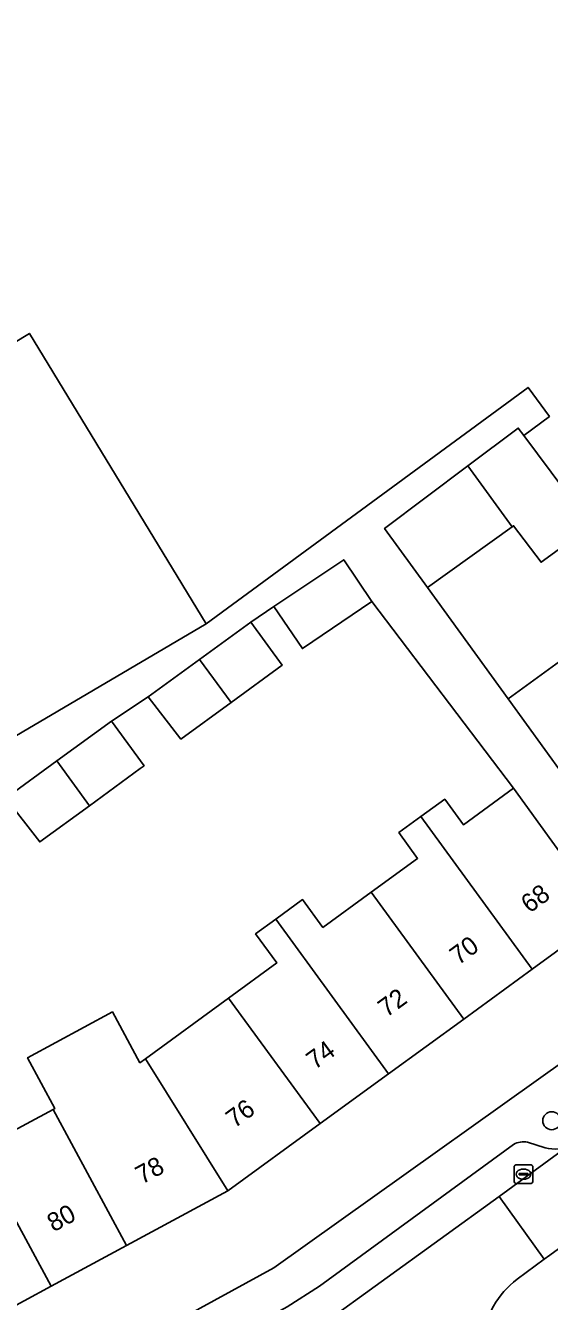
# Model space of a CAD drawing. Extents: x 159817 to 160765, y 380688 to 381638.
# Drawn here: x 159915.8 to 159944.3, y 381366.6 to 381436.1 of the extents above; entities that cross this region are included whole.
import ezdxf

# ---------------------------------------------------------------- set-up
doc = ezdxf.new("R2010")
doc.units = 0
for name, color, linetype in [('IMGEO_Boom', 7, 'Continuous'), ('IMGEO_Erf', 7, 'Continuous'), ('IMGEO_Kolk', 7, 'Continuous'), ('IMGEO_Pand', 7, 'Continuous'), ('IMGEO_Pand_nummerreeks', 7, 'Continuous'), ('IMGEO_Parkeervlak_open', 7, 'Continuous'), ('IMGEO_Rijbaan_lokaal_open', 7, 'Continuous'), ('IMGEO_Voetpad_open', 7, 'Continuous')]:
    doc.layers.add(name, color=color, linetype=linetype)

msp = doc.modelspace()

# ---------------------------------------------------------------- linework, layer by layer
at = {"layer": 'IMGEO_Boom'}
msp.add_circle((159944.457, 381376.478), 0.489, dxfattribs=at)
at = {"layer": 'IMGEO_Erf'}
for points in [[(159878.875, 381396.888), (159916.025, 381419.326), (159925.649, 381403.516), (159943.166, 381416.395), (159944.328, 381414.815), (159942.937, 381413.777), (159946.609, 381408.857), (159943.877, 381406.876), (159942.384, 381408.857), (159942.302, 381408.798), (159937.694, 381405.502), (159942.078, 381399.432), (159946.679, 381402.779)], [(159914.391, 381375.519), (159917.308, 381377.095), (159917.41, 381377.15), (159915.922, 381379.906), (159920.542, 381382.402), (159922.036, 381379.635), (159922.336, 381379.854), (159926.865, 381383.154), (159929.485, 381385.063), (159928.333, 381386.644), (159929.444, 381387.453), (159930.895, 381388.51), (159931.998, 381386.996), (159934.631, 381388.914), (159937.157, 381390.754), (159936.135, 381392.156), (159937.332, 381393.028), (159938.635, 381393.977), (159939.647, 381392.588), (159942.37, 381394.572), (159934.668, 381404.735), (159930.882, 381402.174), (159929.335, 381404.461), (159928.075, 381403.617), (159929.786, 381401.273), (159927.012, 381399.247), (159924.272, 381397.247), (159922.493, 381399.54), (159920.495, 381398.229), (159922.27, 381395.797), (159922.061, 381395.644), (159919.287, 381393.619), (159916.589, 381391.649), (159914.744, 381394.028)]]:
    msp.add_lwpolyline(points, dxfattribs=at)
msp.add_lwpolyline([(159948.981, 381382.473), (159950.421, 381383.521), (159947.411, 381387.653), (159943.387, 381384.722), (159939.664, 381382.009), (159935.58, 381379.034), (159931.849, 381376.317), (159926.83, 381372.66), (159921.311, 381369.679), (159917.205, 381367.462), (159912.776, 381365.069), (159907.785, 381362.373), (159902.815, 381359.689), (159897.692, 381356.922), (159900.122, 381352.484), (159929.338, 381368.476)], close=True, dxfattribs=at)
at = {"layer": 'IMGEO_Kolk'}
for p, q in [((159942.419, 381373.142), (159942.419, 381373.994)), ((159942.494, 381374.068), (159943.346, 381374.068)), ((159942.721, 381373.611), (159943.119, 381373.611)), ((159942.907, 381373.848), (159942.932, 381373.848)), ((159943.42, 381373.994), (159943.42, 381373.142)), ((159943.346, 381373.068), (159942.494, 381373.068)), ((159942.678, 381373.562), (159942.678, 381373.574)), ((159943.116, 381373.525), (159942.718, 381373.525)), ((159942.93, 381373.288), (159942.905, 381373.288)), ((159943.162, 381373.574), (159943.162, 381373.562))]:
    msp.add_line(p, q, dxfattribs=at)
for points in [[(159942.419, 381373.142), (159942.419, 381373.994)], [(159942.494, 381374.068), (159943.346, 381374.068)], [(159943.42, 381373.994), (159943.42, 381373.142)], [(159943.346, 381373.068), (159942.494, 381373.068)]]:
    msp.add_lwpolyline(points, dxfattribs=at)
for centre, radius, start, end in [((159942.496, 381373.992), 0.0765, 91.55205, 178.44795), ((159942.496, 381373.992), 0.0765, 91.55205, 178.44795), ((159942.718, 381373.571), 0.0403, 85.87752, 175.75265), ((159943.123, 381373.573), 0.0386, 1.73085, 96.63898), ((159943.344, 381373.992), 0.0765, 1.55205, 88.44795), ((159943.344, 381373.992), 0.0765, 1.55205, 88.44795), ((159942.496, 381373.144), 0.0765, 181.55205, 268.44795), ((159942.496, 381373.144), 0.0765, 181.55205, 268.44795), ((159942.715, 381373.561), 0.0366, 178.93798, 274.71019), ((159943.119, 381373.568), 0.043, 264.86636, 352.45326), ((159943.344, 381373.144), 0.0765, 271.55205, 358.44795), ((159943.344, 381373.144), 0.0765, 271.55205, 358.44795)]:
    msp.add_arc(centre, radius, start, end, dxfattribs=at)
for centre, major_axis, ratio, start_param, end_param in [((159942.906, 381373.568), (-0.387, 0.002), 0.722429, 4.712389, 7.853982), ((159942.931, 381373.568), (-0.39, 0.002), 0.717154, 1.570796, 4.712389)]:
    msp.add_ellipse(centre, major_axis=major_axis, ratio=ratio, start_param=start_param, end_param=end_param, dxfattribs=at)
at = {"layer": 'IMGEO_Pand'}
for points in [[(159925.649, 381403.516), (159916.025, 381419.326), (159878.875, 381396.888), (159888.162, 381381.468), (159889.129, 381382.037)], [(159942.937, 381413.777), (159942.638, 381414.177), (159939.889, 381412.116), (159942.302, 381408.798), (159942.384, 381408.857), (159943.877, 381406.876), (159946.609, 381408.857)], [(159939.889, 381412.116), (159935.361, 381408.72), (159937.694, 381405.502), (159942.302, 381408.798)], [(159933.133, 381407.006), (159929.335, 381404.461), (159930.882, 381402.174), (159934.668, 381404.735)], [(159928.075, 381403.617), (159925.29, 381401.583), (159927.012, 381399.247), (159929.786, 381401.273)], [(159946.843, 381402.553), (159946.679, 381402.779), (159942.078, 381399.432), (159946.086, 381393.922), (159949.028, 381389.878), (159953.628, 381393.224)], [(159925.29, 381401.583), (159922.493, 381399.54), (159924.272, 381397.247), (159927.012, 381399.247)], [(159920.495, 381398.229), (159917.522, 381396.057), (159919.287, 381393.619), (159922.061, 381395.644), (159922.27, 381395.797)], [(159917.522, 381396.057), (159914.744, 381394.028), (159916.589, 381391.649), (159919.287, 381393.619)], [(159937.332, 381393.028), (159943.387, 381384.722), (159947.411, 381387.653), (159944.466, 381391.695), (159942.37, 381394.572), (159939.647, 381392.588), (159938.635, 381393.977)], [(159939.664, 381382.009), (159943.387, 381384.722), (159937.332, 381393.028), (159936.135, 381392.156), (159937.157, 381390.754), (159934.631, 381388.914)], [(159934.631, 381388.914), (159931.998, 381386.996), (159930.895, 381388.51), (159929.444, 381387.453), (159935.58, 381379.034), (159939.664, 381382.009)], [(159931.849, 381376.317), (159935.58, 381379.034), (159929.444, 381387.453), (159928.333, 381386.644), (159929.485, 381385.063), (159926.865, 381383.154)], [(159931.849, 381376.317), (159926.865, 381383.154), (159922.336, 381379.854), (159926.83, 381372.66)], [(159917.308, 381377.095), (159921.311, 381369.679), (159926.83, 381372.66), (159922.336, 381379.854), (159922.036, 381379.635), (159920.542, 381382.402), (159915.922, 381379.906), (159917.41, 381377.15)], [(159912.076, 381376.962), (159917.205, 381367.462), (159921.311, 381369.679), (159917.308, 381377.095), (159914.391, 381375.519), (159913.265, 381377.604)], [(159912.076, 381376.962), (159907.792, 381374.648), (159907.648, 381374.57), (159912.776, 381365.069), (159917.205, 381367.462)]]:
    msp.add_lwpolyline(points, close=True, dxfattribs=at)
at = {"layer": 'IMGEO_Parkeervlak_open'}
for points in [[(159942.382, 381375.189), (159931.813, 381367.471), (159930.062, 381366.351), (159925.659, 381363.938)], [(159941.589, 381372.352), (159945.51, 381375.214)], [(159944.096, 381375.007), (159943.137, 381375.314)], [(159929.496, 381363.976), (159931.961, 381365.382), (159941.589, 381372.352)]]:
    msp.add_lwpolyline(points, dxfattribs=at)
for centre, radius, start, end in [((159942.956, 381374.062), 1.265, 81.79187, 117.00969), ((159944.582, 381376.619), 1.683, 253.21214, 303.44497)]:
    msp.add_arc(centre, radius, start, end, dxfattribs=at)
at = {"layer": 'IMGEO_Rijbaan_lokaal_open'}
msp.add_lwpolyline([(159967.167, 381385.74), (159964.661, 381389.178), (159949.818, 381378.361), (159945.51, 381375.214), (159941.589, 381372.352), (159944.041, 381368.933), (159944.348, 381369.151), (159953.636, 381375.926)], close=True, dxfattribs=at)
for points in [[(159941.589, 381372.352), (159931.961, 381365.382), (159929.496, 381363.976)], [(159944.041, 381368.933), (159941.589, 381372.352)], [(159942.572, 381367.853), (159944.041, 381368.933)]]:
    msp.add_lwpolyline(points, dxfattribs=at)
msp.add_arc((159945.591, 381363.925), 4.954, 127.55165, 217.93343, dxfattribs=at)
at = {"layer": 'IMGEO_Voetpad_open'}
for points in [[(160025.115, 381437.941), (160006.457, 381424.324), (160006.453, 381424.321), (160003.64, 381422.268), (160000, 381419.611), (159973.223, 381400.119), (159971.191, 381398.64), (159952.534, 381385.059), (159950.421, 381383.521), (159948.981, 381382.473), (159929.338, 381368.476), (159900.122, 381352.484), (159895.831, 381350.135), (159893.13, 381348.697), (159890.213, 381347.131), (159882.744, 381343.216), (159882.026, 381342.84), (159872.678, 381337.949), (159871.877, 381337.552)], [(159946.086, 381393.922), (159942.078, 381399.432), (159937.694, 381405.502), (159935.361, 381408.72), (159939.889, 381412.116), (159942.638, 381414.177), (159942.937, 381413.777), (159944.328, 381414.815), (159943.166, 381416.395), (159925.649, 381403.516), (159889.129, 381382.037)], [(159914.744, 381394.028), (159917.522, 381396.057), (159920.495, 381398.229), (159922.493, 381399.54), (159925.29, 381401.583), (159928.075, 381403.617), (159929.335, 381404.461), (159933.133, 381407.006), (159934.668, 381404.735), (159942.37, 381394.572), (159944.466, 381391.695)], [(159925.659, 381363.938), (159930.062, 381366.351), (159931.813, 381367.471), (159942.382, 381375.189)], [(159943.137, 381375.314), (159944.096, 381375.007)], [(159944.348, 381369.151), (159944.041, 381368.933), (159942.572, 381367.853)]]:
    msp.add_lwpolyline(points, dxfattribs=at)
for centre, radius, start, end in [((159942.956, 381374.062), 1.265, 81.79187, 117.00969), ((159944.582, 381376.619), 1.683, 253.21214, 303.44497), ((159945.591, 381363.925), 4.954, 127.55165, 217.93343)]:
    msp.add_arc(centre, radius, start, end, dxfattribs=at)

# ---------------------------------------------------------------- texts
at = {"layer": 'IMGEO_Pand_nummerreeks'}
for s, rotation, p in [('68', 36.07238, (159943.249, 381387.739)), ('70', 36.07238, (159939.376, 381384.917)), ('72', 36.06039, (159935.467, 381382.071)), ('74', 36.08031, (159931.562, 381379.227)), ('76', 36.07452, (159927.188, 381376.04)), ('78', 28.37504, (159922.148, 381372.996)), ('80', 28.37504, (159917.336, 381370.397))]:
    msp.add_text(s, height=1, rotation=rotation, dxfattribs=at).set_placement(p)

doc.saveas('drawing.dxf')
